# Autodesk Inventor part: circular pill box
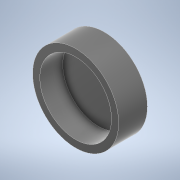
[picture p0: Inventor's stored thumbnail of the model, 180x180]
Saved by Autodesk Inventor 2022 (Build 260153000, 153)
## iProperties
Created: 2021-06
Part Number: circular pill box
Material: Acetal Resin, Black
Document SubType Name: Modeling
Designer: USER
Density: 1.425 g/cm^3
Appearance: Smooth - Black
Author: USER
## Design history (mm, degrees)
sketch "Sketch2"
  geometry: C1 r 30 at (0, 0); 1 further point
  constraints: 1 centre point, 1 coincident
  dimensions: "d3" = 60 diameter of C1
extrude "Extrusion2" new body sketch "Sketch2" distance "d4" = 20; taper "d5" = 0 deg
sketch "Sketch3"
  geometry: C1 r 25 at (0, 0); 1 further point
  constraints: 1 centre point, 1 coincident
  dimensions: "d6" = 50 diameter of C1
extrude "Extrusion3" cut sketch "Sketch3" distance "d7" = 16; taper "d8" = 0 deg
sketch "Sketch4"
  geometry: C1 r 5 at (15, 0); 1 further point
  constraints: 1 centre point
  dimensions: "d11" = 15 distance of C1.centre point (0, 0); "d12" = 10 diameter of C1
extrude "Extrusion4" cut sketch "Sketch4" extent not by distance; stored distance "d9" = 0; taper "d10" = 0 deg
body "Solid2"
